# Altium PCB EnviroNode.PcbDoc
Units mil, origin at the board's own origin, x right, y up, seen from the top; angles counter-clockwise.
Board outline 1178.98 x 1062.99 mil, 2 copper layers (Top Layer, Bottom Layer); 21 components, 18 nets, 108 pads, 13 vias.
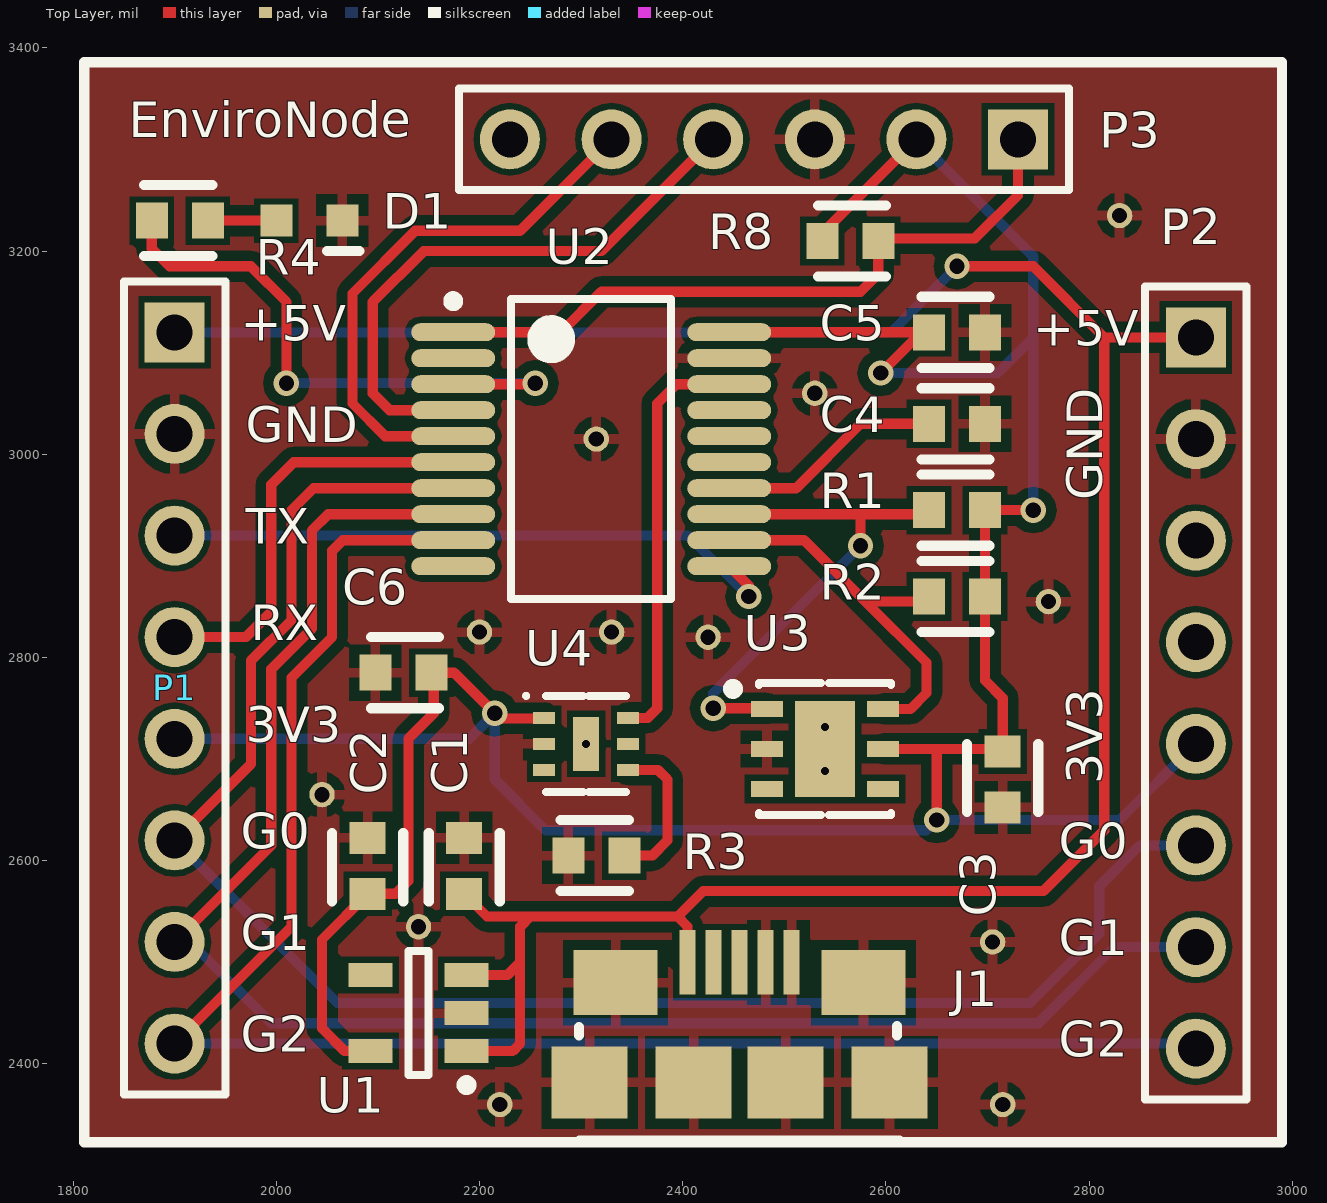
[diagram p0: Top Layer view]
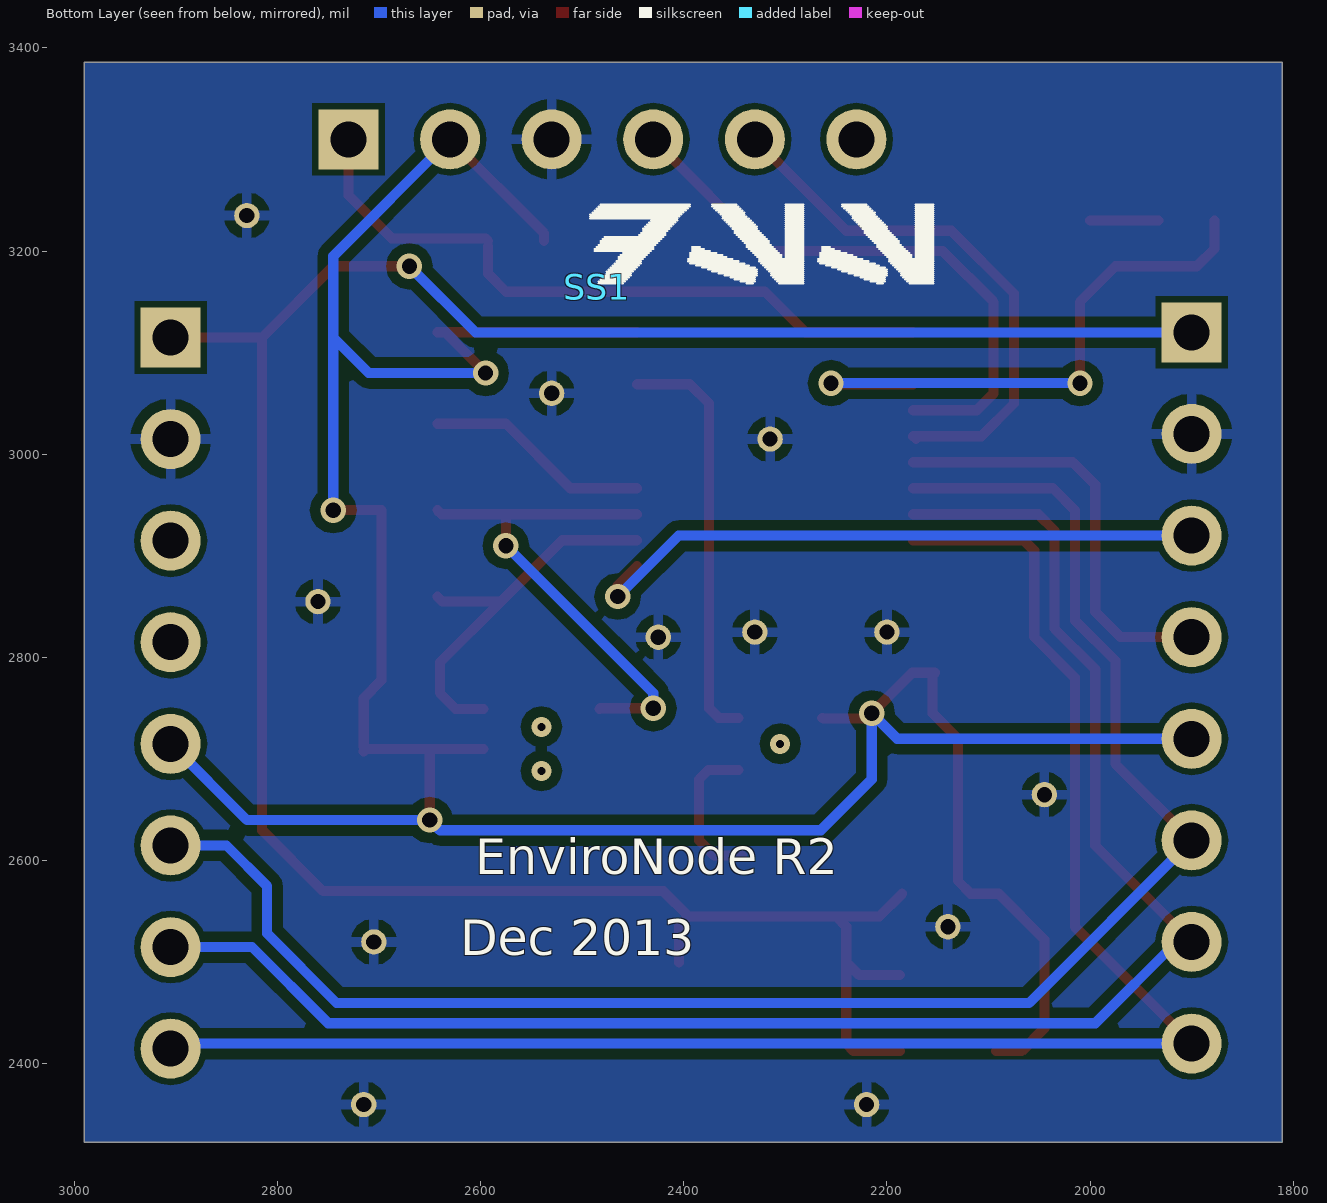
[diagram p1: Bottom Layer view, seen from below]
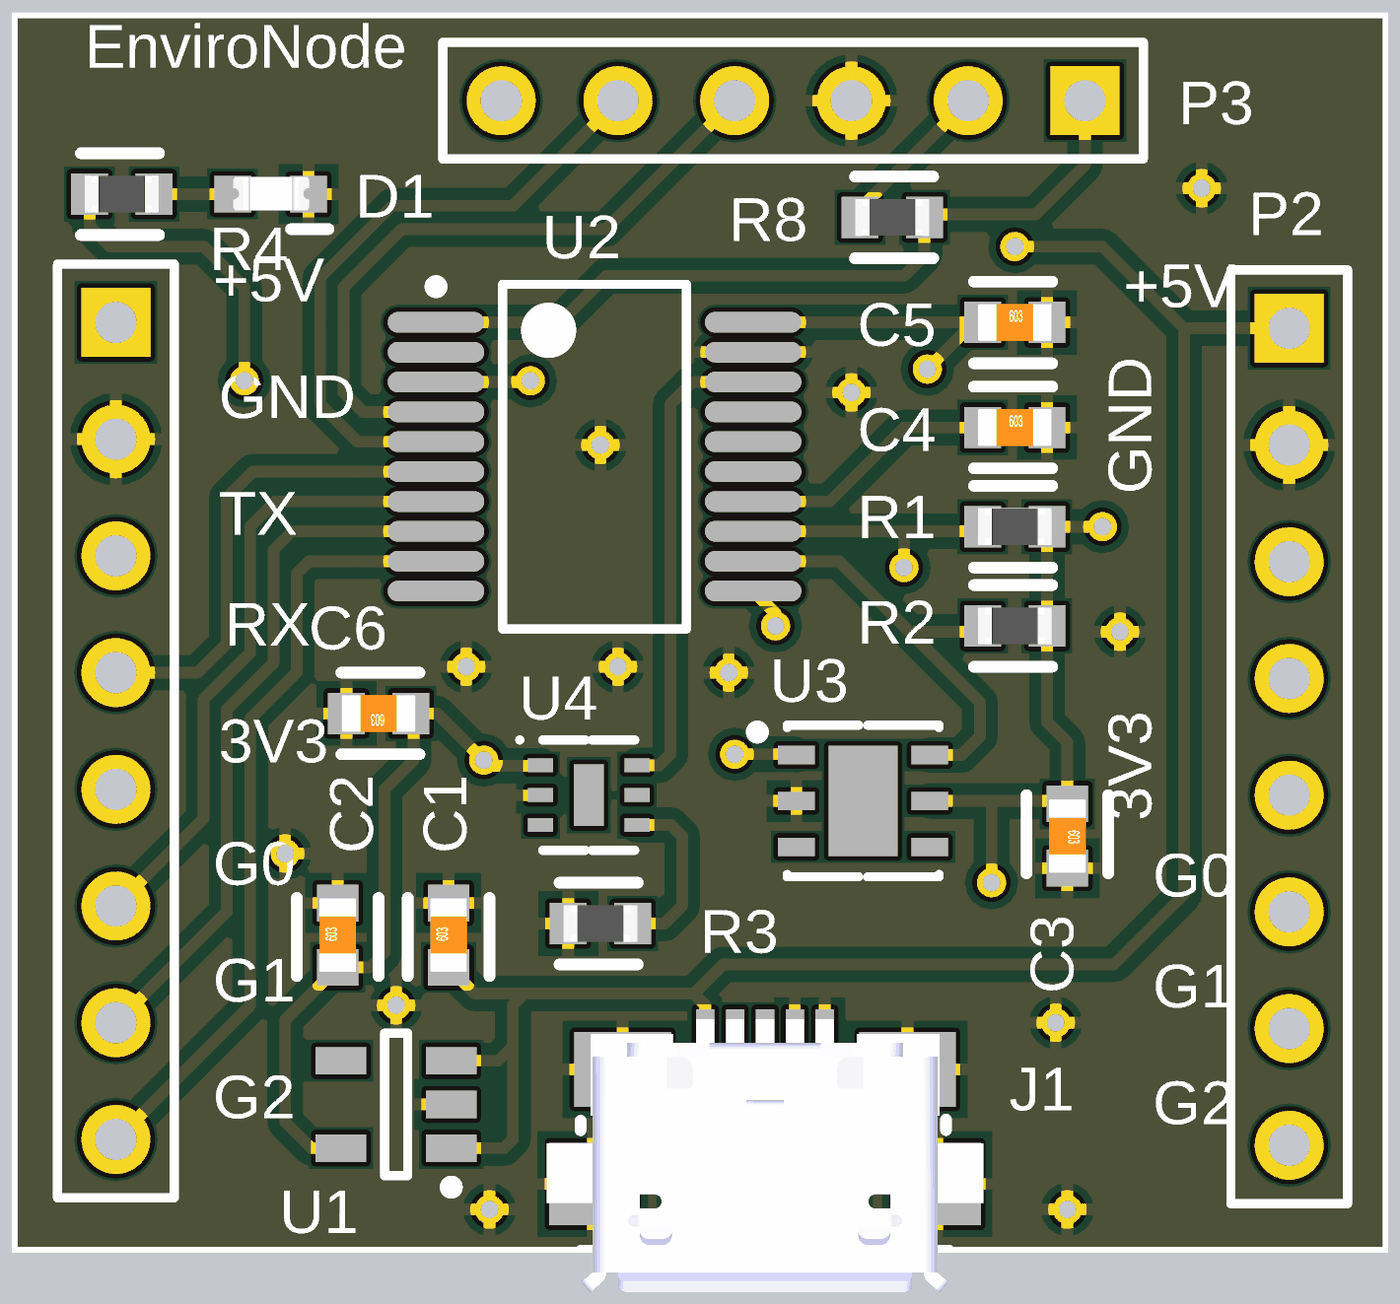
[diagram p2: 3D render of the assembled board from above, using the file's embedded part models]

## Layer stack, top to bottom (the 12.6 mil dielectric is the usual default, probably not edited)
Top Solder: solder mask 0.4, Solder Resist, Dk 3.5
Top Layer: signal copper 1.4
Dielectric1: dielectric 12.6, FR-4, Dk 4.8
Bottom Layer: signal copper 1.4
Bottom Solder: solder mask 0.4, Solder Resist, Dk 3.5

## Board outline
1811.02,2322.83 1811.02,3385.83 2990,3385.83 2990,2322.83

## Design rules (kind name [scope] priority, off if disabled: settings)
Clearance ClearancePads [All vs IsPad] p1: gap=6
Clearance [All] p2: gap=10
PolygonConnect [All] p1: connectstyle=Relief reliefconductorwidth=10 reliefentries=4 polygonreliefangle="90 Angle" airgapwidth=10
RoutingVias [All] p1: holewidth=15 width=25 viastyle="Through Hole" minholewidth=15 minwidth=25 maxholewidth=15 maxwidth=25
SolderMaskExpansion [All] p1: expansion=4
Width WidthPower [InNetClass('Power')] p1: maxlimit=20 minlimit=10 preferedwidth=20
Width [All] p2: maxlimit=10 minlimit=10 preferedwidth=10
29 further rules are at their usual default settings.

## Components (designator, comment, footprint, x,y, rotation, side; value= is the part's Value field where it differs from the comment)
C1 "CC0603KRX7R9BB104" C0603 2185,2595 r90 top
C2 "CC0603KRX7R9BB104" C0603 2090,2595 r90 top
C3 "CC0603KRX7R9BB104" C0603 2715,2680 r270 top
C4 "CC0603KRX7R9BB104" C0603 2670,3030 r0 top
C5 "CC0603KRX7R9BB104" C0603 2670,3120 r0 top
C6 "CC0603KRX7R9BB104" C0603 2125,2785 r180 top
D1 "LTST-C190KGKT" LED_0603 1965,3195 r0 top
J1 "10118192-0001LF" FCI/10118192-0001LF 2250,2270 r0 top
P1 "Header 8" HDR1X8 1900,3120 r270 top
P2 "Header 8" HDR1X8 2905,3115 r270 top
P3 "PIC ICSP" HDR1X6 2730,3310 r180 top
R1 "ERJ-3EKF1002V" R0603 2670,2945 r0 top
R2 "ERJ-3EKF1002V" R0603 2670,2860 r0 top
R3 "ERJ-3EKF1003V" R0603 2315,2605 r0 top
R4 "ERJ-3GEYJ331V" R0603 1905,3230 r0 top
R8 "ERJ-3EKF1002V" R0603 2565,3210 r180 top
SS1 "DSS" DSS_LOGO 2485,3165 r180 bottom
U1 "TPS73233DBVT" TI-DBV5_N 2140,2450 r180 top
U2 "PIC24FV16KA301-E/SS" MCHP-SSOP-SS20_N 2310,3005 r0 top
U3 "HPP828E031" DFN-6 2540,2710 r0 top
U4 "ISL76671AROZ-T7A" ODFN-6 2305,2715 r0 top

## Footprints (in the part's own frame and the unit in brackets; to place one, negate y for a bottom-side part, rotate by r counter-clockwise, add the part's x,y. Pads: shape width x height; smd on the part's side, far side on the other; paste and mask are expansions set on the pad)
C0603 [mm] "Chip Capacitor, Body 1.6x0.8mmx0.9mm"
  rect 0.8x0.9 smd: 1(-0.7,0) 2(0.7,0)
  silkscreen extent -0.89,-0.89 0.81,0.89, body extent -0.8,-0.4 0.8,0.4, height 0.3
DFN-6 [mm]
  rect 0.8x0.4 smd: 1(-1.45,1) 2(-1.45,0) 3(-1.45,-1) 4(1.45,-1) 5(1.45,0) 6(1.45,1)
  rect 1.5x2.4 smd: 7(0,0)
  silkscreen extent -2.42,-1.65 1.65,1.65, body extent -1.5,-1.5 1.5,1.5, height 0.9
DSS_LOGO [mil]
  silkscreen extent -7,3 331,81
FCI/10118192-0001LF [mm] "USB Micro B, all surface mount, no holes"
  rect 0.4x1.604 smd: 1(3.932,5.842) 2(4.582,5.842) 3(5.232,5.842) 4(5.882,5.842) 5(6.532,5.842)
  rect 1.9x1.8 smd: 6(1.486,2.84) 6(4.082,2.84) 6(6.382,2.84) 6(8.978,2.84)
  rect 2.103x1.622 smd: 6(2.134,5.334) 6(8.331,5.334)
  silkscreen extent 1.22,1.39 9.23,4.24, body extent 0.48,0.49 9.98,6.43, height 2.74
HDR1X6 [mm] "Connector; Header; 6 Position"
  rect 1.5x1.5 hole 0.9: 1(0,0)
  round 1.5 hole 0.9: 2(2.54,0) 3(5.08,0) 4(7.62,0) 5(10.16,0) 6(12.7,0)
  silkscreen extent -1.27,-1.27 13.97,1.27
HDR1X8 [mm] "Connector; Header; 8 Position"
  rect 1.5x1.5 hole 0.9: 1(0,0)
  round 1.5 hole 0.9: 2(2.54,0) 3(5.08,0) 4(7.62,0) 5(10.16,0) 6(12.7,0) 7(15.24,0) 8(17.78,0)
  silkscreen extent -1.27,-1.27 19.05,1.27
LED_0603 [mm]
  rect 0.8x0.8 smd: 1(0.889,0.889) 2(2.539,0.889)
  silkscreen extent 2.16,0.13 2.97,0.13, body extent 0.9,0.53 2.55,1.26, height 0.68
MCHP-SSOP-SS20_N [mm] "SOP, 20-Leads, Body 7.2x5.3mm, Pitch 0.65mm, IPC Medium Density"
  oval 2.1x0.45 smd: 1(-3.45,2.925) 2(-3.45,2.275) 3(-3.45,1.625) 4(-3.45,0.975) 5(-3.45,0.325) 6(-3.45,-0.325) 7(-3.45,-0.975) 8(-3.45,-1.625) 9(-3.45,-2.275) 10(-3.45,-2.925) 11(3.45,-2.925) 12(3.45,-2.275) 13(3.45,-1.625) 14(3.45,-0.975) 15(3.45,-0.325) 16(3.45,0.325) 17(3.45,0.975) 18(3.45,1.625) 19(3.45,2.275) 20(3.45,2.925)
  silkscreen extent -3.57,-3.75 2,3.82, body extent -2.8,-3.75 2.8,3.75, height 2
ODFN-6 [mm]
  rect 0.55x0.3 smd: 1(-1.05,0.65) 2(-1.05,0) 3(-1.05,-0.65) 4(1.05,-0.65) 5(1.05,0) 6(1.05,0.65)
  rect 0.65x1.35 smd: 7(0,0)
  silkscreen extent -1.55,-1.2 1,1.25, body extent -1,-1.05 1,1.05, height 0.75
R0603 [mm] "Chip Resistor, Body 1.6x0.8mmx0.9mm"
  rect 0.8x0.9 smd: 1(-0.7,0) 2(0.7,0)
  silkscreen extent -0.89,-0.89 0.81,0.89, body extent -0.8,-0.4 0.8,0.4, height 0.37
TI-DBV5_N [mm] "SOT23, 5-Leads, Body 2.9x1.6mm, Pitch 0.95mm, IPC Medium Density"
  rect 1.1x0.6 smd: 1(-1.2,0.95) 2(-1.2,0) 3(-1.2,-0.95) 4(1.2,-0.95) 5(1.2,0.95)
  silkscreen extent -1.33,-1.55 0.25,1.92, body extent -0.87,-1.52 0.87,1.53, height 1.45

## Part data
C1 C2 C3 C4 C5 C6: "CAP CER 0.1UF 50V 10% X7R 0603"
D1: "LED GREEN CLEAR 0603 SMD"
J1: "CONN USB MICRO B RECPT SMT R/A"
P1 P2: "Header, 8-Pin"
P3: library part PIC_ICSP, "Microchip PIC In-Circuit Serial Programmer Connector"
R1 R2 R8: "RES 10.0K OHM 1/10W 1% 0603 SMD"
R3: "RES 100K OHM 1/10W 1% 0603 SMD"
R4: "RES 330 OHM 1/10W 5% 0603 SMD"
U1: "Single Output Fast Transient Response LDO, 200 mA, Fixed 3.3 V Output, 1.7 to 5.5 V Input, with Reverse Current Protection, 5-pin SOT-23 (DBV), -40 to 85 degC, Green (RoHS & no Sb/Br)"
U2: "General Purpose, 16-Bit Flash Microcontroller with XLP Technology, 16 MIPS, 18 I/O, -40 to 125 degC, 20-pin SSOP (SS20), Tube"
U3: "IC SENSOR TEMP/HUM DGTL"
U4: "IC AMBIENT LIGHT SENSOR"

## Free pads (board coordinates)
  round 25 hole 15: 0(2045,2665) 0(2140,2535) 0(2200,2825) 0(2220,2360) 0(2315,3015) 0(2330,2825) 0(2425,2820) 0(2530,3060) 0(2705,2520) 0(2715,2360) 0(2760,2855) 0(2830,3235)

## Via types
v1: diameter 25, hole 15, Top Layer to Bottom Layer, 10 vias
v2: diameter 19.68, hole 7.87, Top Layer to Bottom Layer, 3 vias

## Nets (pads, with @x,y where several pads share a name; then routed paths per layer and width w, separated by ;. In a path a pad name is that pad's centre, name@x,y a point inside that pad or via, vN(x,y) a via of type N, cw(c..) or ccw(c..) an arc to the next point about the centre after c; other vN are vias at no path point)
+3V3: C2.1 C3.1 C5.1 C6.1 P1.5 P2.5 P3.2 R1.2 R2.2 R8.2 U1.5 U2.20 U3.5 U4.1 | length 3202.2
  Top Layer w10: U1.5 2067.4,2412.6 2045,2435 2045,2522.44 C2.1 2117.44,2567.44 2130,2580 2130,2720 2155,2745 2155,2782.56 C6.1 2175,2785 v1(2215,2745) 2220,2740 2263.07,2740 U4.1 ; U2.20 2642.28,3120.16 C5.1 2635,3120 v1(2595,3080) ; R8.2 2537.44,3217.44 P3.2 ; U3.5 2650,2710 ; v1(2650,2640) 2650,2710 ; C3.1 C3.1@2712.56,2710 ; v1(2745,2945) R1.2 R2.2 2697.56,2777.44 2715,2760 2715,2712.44 C3.1@2712.56,2710 ; P2.5@2897.56,2707.56 P2.5 ; 2650,2710 C3.1@2712.56,2710
  Bottom Layer w10: P1.5 2190,2720 v1(2215,2745) 2215,2680 2265,2630 2640,2630 v1(2650,2640) 2830,2640 P2.5 ; v1(2595,3080) 2710,3080 2745,3115 ; P3.2 2745,3195 2745,3115 ; v1(2745,2945) 2745,3115
+5V: C1.1 J1.1 P1.1 P2.1 U1.1 U1.3 | length 2512.4
  Top Layer w10: C1.1 2207.44,2545 2250,2545 ; U1.1 2232.6,2412.6 2240,2420 2240,2500 ; U1.3 2227.4,2487.4 2240,2500 ; J1.1 2404.82,2535.18 2395,2545 ; v1(2670,3185) 2745,3185 2815,3115 ; P2.1 2815,3115 ; 2240,2500 2240,2535 2250,2545 ; 2250,2545 2395,2545 ; 2395,2545 2420,2570 2755,2570 2815,2630 2815,3115
  Bottom Layer w10: P1.1 2605,3120 v1(2670,3185)
G0: P1.6 P2.6 U2.7 | length 1703.6
  Top Layer w10: P1.6 1975,2695 1975,2796.72 2015,2836.72 2015,2945 2036.61,2966.61 U2.7
  Bottom Layer w10: P1.6 2060,2460 2741.72,2460 2810,2528.28 2810,2575 2850,2615 P2.6
G1: P1.7 P2.7 U2.8 | length 1675.9
  Top Layer w10: P1.7 1995,2615 1995,2788.43 2035,2828.43 2035,2925 2051.02,2941.02 U2.8
  Bottom Layer w10: P1.7 1915,2520 1995,2440 2750,2440 2825,2515 P2.7
G2: P1.8 P2.8 U2.9 | length 1679.8
  Top Layer w10: P1.8 2015,2535 2015,2780.15 2055,2820.15 2055,2905 2065.43,2915.43 U2.9
  Bottom Layer w10: P1.8 2900,2420 P2.8
GND: C1.2 C2.2 C3.2 C4.2 C5.2 C6.2 D1.2 J1.4 J1.5 J1.6 P1.2 P2.2 P3.3 pad.0 R3.1 U1.2 U2.19 U3.2 U4.2
MCLR: P3.1 R8.1 U2.1 | length 680.7
  Top Layer w10: U2.1 2280.16,3120.16 2320,3160 2575,3160 2592.56,3177.56 R8.1@2592.56,3205 ; R8.1 2595.06,3212.5 2687.5,3212.5 2730,3255 P3.1
NetC4_1: C4.1 U2.14 | length 222.9
  Top Layer w10: U2.14 2511.61,2966.61 2575,3030 C4.1
NetD1_1: D1.1 R4.2 | length 67.4
  Top Layer w10: R4.2 D1.1
NetR3_2: R3.2 U4.4 | length 151.2
  Top Layer w10: R3.2 2370,2605 2385,2620 2385,2680 2375.59,2689.41 U4.4
NetR4_1: R4.1 U2.3 | length 588
  Top Layer w10: R4.1 1877.44,3202.56 1895,3185 1975,3185 2010,3150 v1(2010,3070) ; U2.3 2253.98,3068.98 v1(2255,3070)
  Bottom Layer w10: v1(2010,3070) v1(2255,3070)
PGC: P3.5 U2.5 | length 542.6
  Top Layer w10: U2.5@2171.38,3015 U2.5 2107.2,3017.8 2075,3050 2075,3158.28 2136.72,3220 2240,3220 P3.5
PGD: P3.4 U2.4 | length 577.3
  Top Layer w10: U2.4 2111.61,3043.39 2095,3060 2095,3150 2145,3200 2320,3200 P3.4
RX_IN: P1.4 U2.6 | length 418.7
  Top Layer w10: P1.4 1970,2820 1995,2845 1995,2970 2017.2,2992.2 U2.6
SCL: R2.1 U2.12 U3.6 | length 388
  Top Layer w10: U2.12 2519.57,2915.43 2580,2855 ; U3.6 2624.37,2749.37 2640,2765 2640,2795 2580,2855 ; R2.1 2637.44,2855 2580,2855
SDA: R1.1 U2.13 U3.1 | length 502.5
  Top Layer w10: v1(2430,2750) 2482.28,2750 U3.1 ; U2.13 2575,2941.02 ; v1(2575,2910) 2575,2941.02 ; R1.1 2638.46,2941.02 2575,2941.02
  Bottom Layer w10: v1(2430,2750) 2430,2765 v1(2575,2910)
TX_OUT: P1.3 U2.11 | length 627.6
  Top Layer w10: U2.11 2465,2870.67 v1(2465,2860)
  Bottom Layer w10: P1.3 2405,2920 v1(2465,2860)
V_LIGHT: U2.18 U4.6 | length 411.2
  Top Layer w10: U4.6 2365.59,2740.59 2375,2750 2375,3050 2393.98,3068.98 U2.18
pads on no net: J1.2 J1.3 P2.3 P2.4 P3.6 U1.4 U2.2 U2.10 U2.15 U2.16 U2.17 U3.3 U3.4 U3.7 U4.3 U4.5 U4.7
copper on no net:
  other v2: 2540,2688.35 2305,2715 2540,2731.65

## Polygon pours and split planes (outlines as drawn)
GND on Bottom Layer "Top Layer-No Net1" (solid, pour order 6): 1811.02,2322.83 1811.02,3385.83 2990,3385.83 2990,2322.83
GND on Top Layer "Top Layer-No Net" (solid, remove dead copper, pour order 4): 1811.02,2322.83 1811.02,3385.83 2990,3385.83 2990,2322.83

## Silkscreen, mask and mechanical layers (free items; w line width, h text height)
Top Overlay:
  the board outline again, w10
  text "EnviroNode" at 1855,3300 h60
  text "+5V" at 1965,3100 h60
  text "+5V" at 2745,3095 h60
  text "GND" at 1970,3000 h60
  text "GND" at 2825,2955 h60 r90
  text "TX" at 1970,2900 h60
  text "RX" at 1975,2805 h60
  text "3V3" at 1970,2705 h60
  text "3V3" at 2825,2675 h60 r90
  text "G0" at 1965,2600 h60
  text "G0" at 2770,2590 h60
  text "G1" at 1965,2500 h60
  text "G1" at 2770,2495 h60
  text "G2" at 1965,2400 h60
  text "G2" at 2770,2395 h60
Bottom Overlay:
  text "EnviroNode R2" at 2605,2575 h60
  text "Dec 2013" at 2620,2495 h60
Mechanical 5:
  the board outline again, w1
